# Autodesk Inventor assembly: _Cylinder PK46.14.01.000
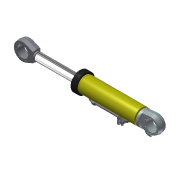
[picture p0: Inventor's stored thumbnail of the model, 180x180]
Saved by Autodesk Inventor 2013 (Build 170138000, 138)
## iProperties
Shininess: 64.0
Length Units: 11269
Angle Units: 11279
Time Units: 11290
Mass Units: 11283
Length Display Precision: 1
Angle Display Precision: 2
Compacted: True
Created: 2004-11
Part Number: _Cylinder PK46.14.01.000
Document SubType Name: Assembly
Designer: ELarisa
Manufacturer: Standard
Standards Organization: Custom
Density: 0.0
Volumn: 0.0
Area: 0.0
PropertySet Name: Model Information
Control State: 0
Master: False
Checked Out: False
Checked Out Date: 2008-10-15
Last Check In Date: 2008-10-15
Author: ELarisa
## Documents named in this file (11)
- C:\Product Design Suite 2013 Test Drive\Model Based Documentation\Workspace\_Cylinder PK46.14.01.000.iam
- C:\Product Design Suite 2013 Test Drive\Model Based Documentation\Workspace\Assemblies\PK46.14.01.010.iam
- C:\Product Design Suite 2013 Test Drive\Model Based Documentation\Workspace\Assemblies\PK46.14.01.020.iam
- C:\Product Design Suite 2013 Test Drive\Model Based Documentation\Workspace\Parts\PK46.14.01.003.ipt
- C:\Product Design Suite 2013 Test Drive\Model Based Documentation\Workspace\Parts\PK46.14.01.004.ipt
- C:\Product Design Suite 2013 Test Drive\Model Based Documentation\Workspace\Parts\PK46.14.01.005.ipt
- C:\Product Design Suite 2013 Test Drive\Model Based Documentation\Workspace\Parts\PK46.14.01.006.ipt
- C:\Product Design Suite 2013 Test Drive\Model Based Documentation\Workspace\Parts\PK46.14.01.015.ipt
- C:\Product Design Suite 2013 Test Drive\Model Based Documentation\Workspace\Parts\PK46.14.01.016.ipt
- C:\Product Design Suite 2013 Test Drive\Model Based Documentation\Workspace\Parts\8.65G.019.ipt
- C:\Product Design Suite 2013 Test Drive\Model Based Documentation\Workspace\Parts\M8-6gx45.58.019(S13).ipt
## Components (12 placed, 10 different names)
1. PK46.14.01.020:1 [sub-assembly] — Insert:80, Mate:7, Mate:9, CylinderStroke, Mate:11, Mate:12, Flush:3
2. PK46.14.01.010:1 [sub-assembly] — Insert:1, Mate:4, Mate:7
3. PK46.14.01.003:1 — Insert:1, CylinderStroke
4. PK46.14.01.004:1 — Insert:80, Insert:81
5. PK46.14.01.005:1 — Insert:81, Insert:82
6. PK46.14.01.006:1 — Insert:82, Mate:11
7. PK46.14.01.015:1 — Flush:1, Mate:5
8. PK46.14.01.016:1 — Flush:2, Mate:5, Insert:88, Insert:89
9. 8.65G.019:25 — Insert:88, Insert:90
10. 8.65G.019:26 — Insert:89, Insert:91
11. M8-6gx45.58.019(S13):1 — Insert:90
12. M8-6gx45.58.019(S13):2 — Insert:91
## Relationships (18: Insert 8, Mate 7, Flush 3)
- Insert:1: PK46.14.01.010:1 ↔ PK46.14.01.003:1
- Insert:80: PK46.14.01.020:1 ↔ PK46.14.01.004:1
- Insert:81: PK46.14.01.004:1 ↔ PK46.14.01.005:1
- Insert:82: PK46.14.01.005:1 ↔ PK46.14.01.006:1
- Flush:1: PK46.14.01.015:1
- Flush:2: PK46.14.01.016:1
- Mate:4: PK46.14.01.010:1
- Mate:5: PK46.14.01.015:1 ↔ PK46.14.01.016:1
- Insert:88: PK46.14.01.016:1 ↔ 8.65G.019:25
- Insert:89: PK46.14.01.016:1 ↔ 8.65G.019:26
- Insert:90: 8.65G.019:25 ↔ M8-6gx45.58.019(S13):1
- Insert:91: 8.65G.019:26 ↔ M8-6gx45.58.019(S13):2
- Mate:7: PK46.14.01.020:1 ↔ PK46.14.01.010:1
- Mate:9: PK46.14.01.020:1
- CylinderStroke [Mate]: PK46.14.01.020:1 ↔ PK46.14.01.003:1
- Mate:11: PK46.14.01.020:1 ↔ PK46.14.01.006:1
- Mate:12: PK46.14.01.020:1
- Flush:3: PK46.14.01.020:1
## Named parameters: CylinderStroke = 325 mm
